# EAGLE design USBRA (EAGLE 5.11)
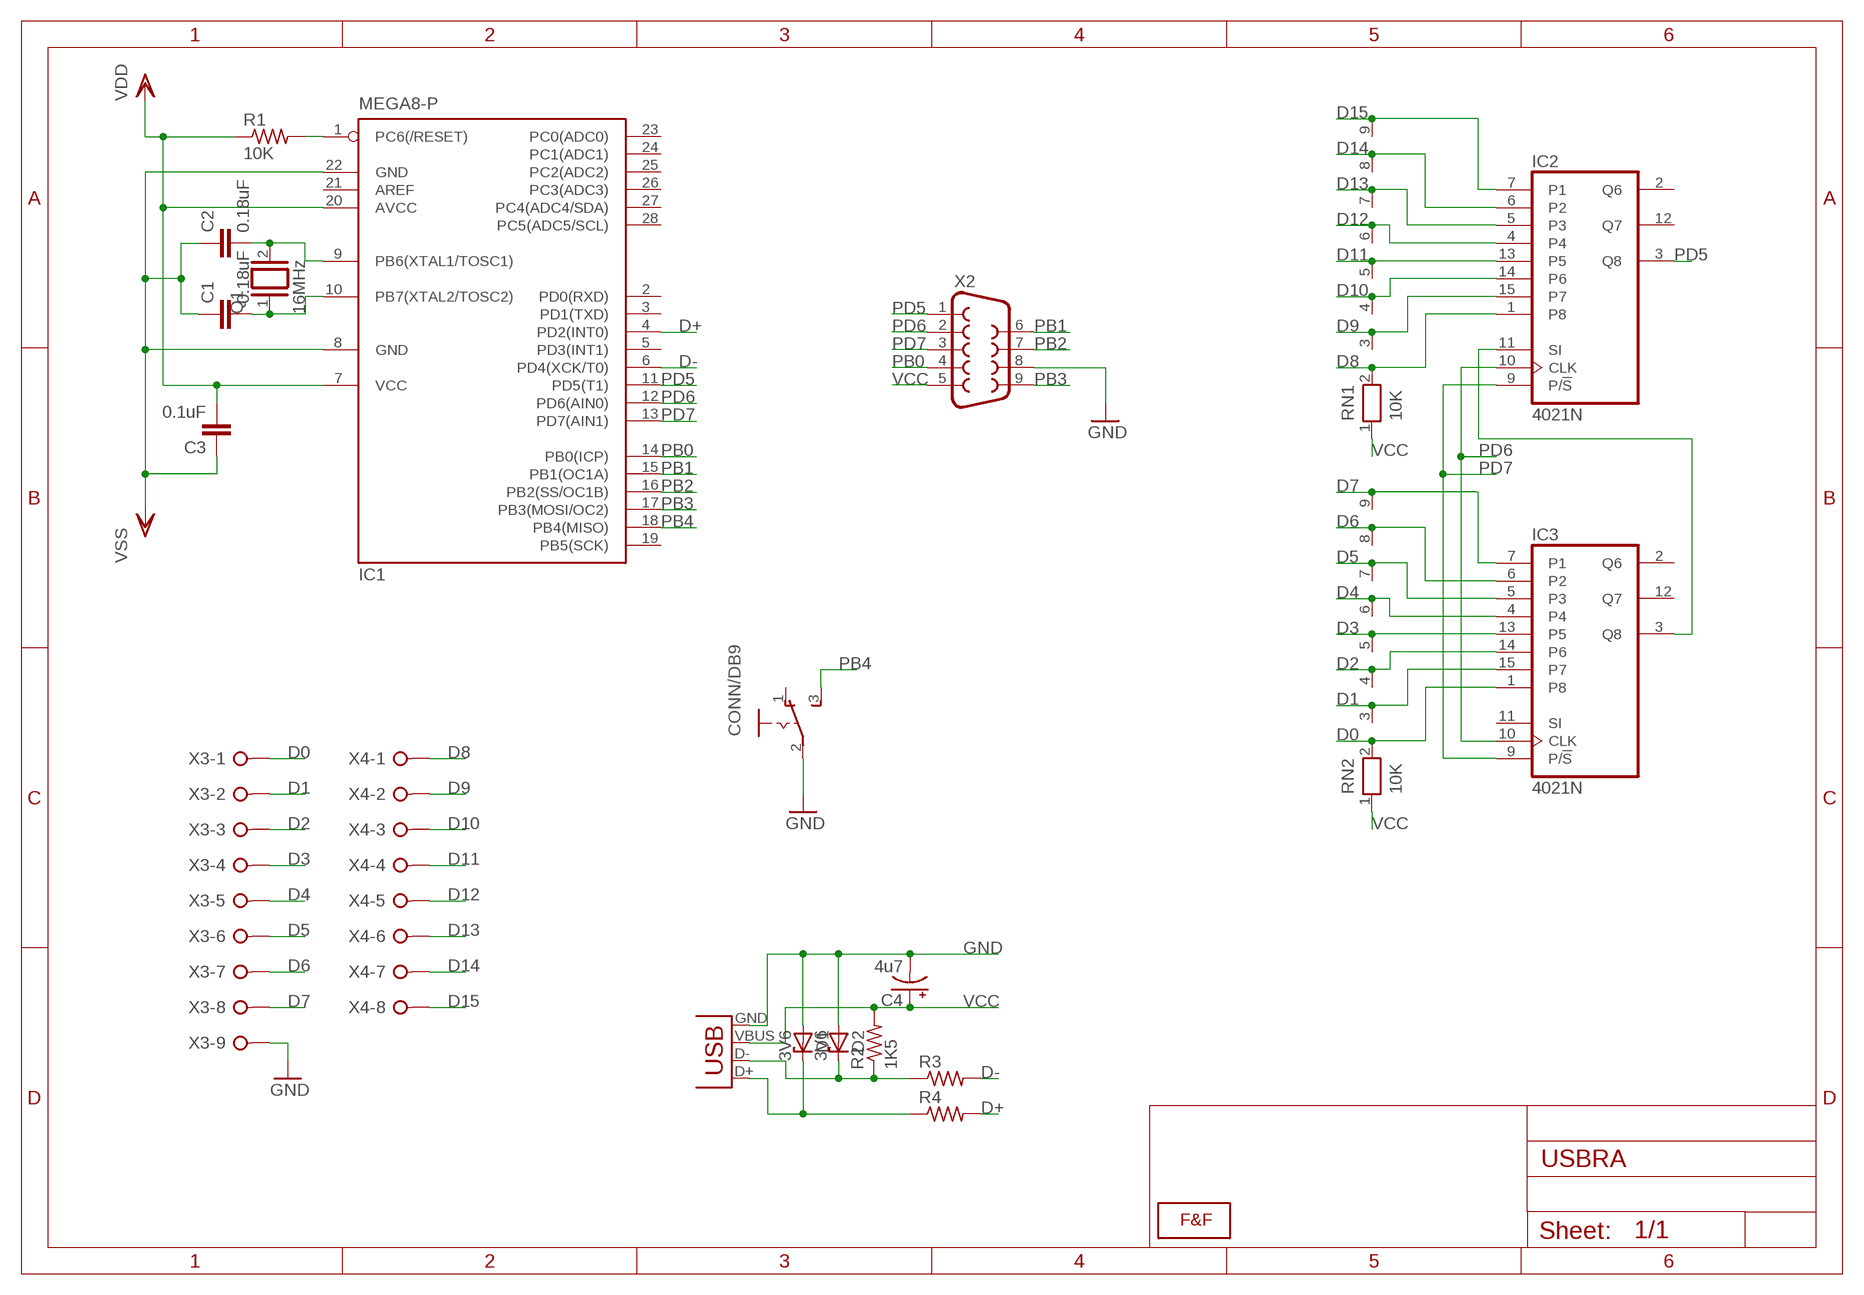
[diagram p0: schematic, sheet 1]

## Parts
C1  0.18uF  CAPPTH  [CAP-PTH-SMALL]
C2  0.18uF  CAPPTH  [CAP-PTH-SMALL]
C3  0.1uF  CAPPTH  [CAP-PTH-SMALL]
C4  4u7  CPOL-USE2.5-6  [E2,5-6]
CONN/DB9  CHAVE  [CHAVE]
D1  3V6  ZENER-DIODEF126-12  [F126Z12]
D2  3V6  ZENER-DIODEF126-12  [F126Z12]
IC1  MEGA8-P  [DIL28-3]
IC2  4021N  [DIL16]
IC3  4021N  [DIL16]
Q1  16MHz  XTAL/S  [QS]
R1  10K  R-US_0207/10  [0207/10]
R2  1K5  R-US_0207/10  [0207/10]
R3  R-US_0207/10  [0207/10]
R4  R-US_0207/10  [0207/10]
RN1  10K  RN08  [RN-9]
RN2  10K  RN08  [RN-9]
U$1  LOGOLOGO_WITH_SMOKE_BIG  [LOGO_BIG]
X1  USBPTH  [USB-B-PTH]
X2  DB9MALE  [DB9_MALE]
X3  W237-09P  [W237-9P]
X4  W237-08P  [W237-8P]

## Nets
D0: IC3.1(P8) RN2.2 X3.1
D1: IC3.15(P7) RN2.3 X3.2
D2: IC3.14(P6) RN2.4 X3.3
D3: IC3.13(P5) RN2.5 X3.4
D4: IC3.4 RN2.6 X3.5
D5: IC3.5(P3) RN2.7 X3.6
D6: IC3.6(P2) RN2.8 X3.7
D7: IC3.7(P1) RN2.9 X3.8
D8: IC2.1(P8) RN1.2 X4.1
D9: IC2.15(P7) RN1.3 X4.2
D10: IC2.14(P6) RN1.4 X4.3
D11: IC2.13(P5) RN1.5 X4.4
D12: IC2.4 RN1.6 X4.5
D13: IC2.5(P3) RN1.7 X4.6
D14: IC2.6(P2) RN1.8 X4.7
D15: IC2.7(P1) RN1.9 X4.8
D+: IC1.4(PD2(INT0)) R4.2
D-: IC1.6(PD4(XCK/T0)) R3.2
GND: C1.1 C2.1 C3.1 C4.- CONN/DB9.2(P) D1.A D2.A IC1.8(GND) IC1.22(GND) X1.GND X2.8 X3.9 ; supply symbol labelled VSS
N$1: IC1.1(PC6(/RESET)) R1.2
N$2: C2.2 IC1.9(PB6(XTAL1/TOSC1)) Q1.2
N$3: C1.2 IC1.10(PB7(XTAL2/TOSC2)) Q1.1
N$4: IC2.11(SI) IC3.3(Q8)
N$8: D1.C R4.1 X1.D+
N$9: D2.C R2.1 R3.1 X1.D-
PB0: IC1.14(PB0(ICP)) X2.4
PB1: IC1.15(PB1(OC1A)) X2.6
PB2: IC1.16(PB2(SS/OC1B)) X2.7
PB3: IC1.17(PB3(MOSI/OC2)) X2.9
PB4: CONN/DB9.3(S) IC1.18(PB4(MISO))
PD5: IC1.11(PD5(T1)) IC2.3(Q8) X2.1
PD6: IC1.12(PD6(AIN0)) IC2.10(CLK) IC3.10(CLK) X2.2
PD7: IC1.13(PD7(AIN1)) IC2.9(P/!S) IC3.9(P/!S) X2.3
VCC: C3.2 C4.+ IC1.7(VCC) IC1.20(AVCC) R1.1 R2.2 RN1.1 RN2.1 X1.VBUS X2.5 ; supply symbol labelled VDD
Unconnected: CONN/DB9.1(O) IC1.2(PD0(RXD)) IC1.3(PD1(TXD)) IC1.5(PD3(INT1)) IC1.19(PB5(SCK)) IC1.21(AREF) IC1.23(PC0(ADC0)) IC1.24(PC1(ADC1)) IC1.25(PC2(ADC2)) IC1.26(PC3(ADC3)) IC1.27(PC4(ADC4/SDA)) IC1.28(PC5(ADC5/SCL)) IC2.2(Q6) IC2.12(Q7) IC3.2(Q6) IC3.11(SI) IC3.12(Q7)

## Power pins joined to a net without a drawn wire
GND: IC2.8(VSS) IC3.8(VSS)
VCC: IC2.16(VDD) IC3.16(VDD)

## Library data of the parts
C1-C3 = SparkFun:CAP: Capacitor
C4 = adafruit:CPOL-US: POLARIZED CAPACITOR, American symbol
CONN/DB9 = switch-fef:CHAVE: chave Verificar
D1 D2 = diode:ZENER-DIODE: Z-Diode
IC1 = atmel:MEGA8-P: MICROCONTROLLER 8 Kbytes FLASH, 1 kbytes SRAM, 512 bytes EEPROM, USART, 4-channel 10 bit ADC, 2-channel 8 bit ADC Pin compatible with Atmega48, ATMega88, ATMega168 Source: avr.lbr; OC_FARNELL: unknown; OC_NEWARK: unknown
IC2 IC3 = 40xx:4021: 8-bit static SHIFT REGISTER
Q1 = special:XTAL/S: CRYSTAL
R1-R4 = adafruit:R-US_: RESISTOR, American symbol
RN1 RN2 = resistor-net:RN08: RESISTOR NETWORK; OC_FARNELL: unknown; OC_NEWARK: unknown
U$1 = F&F:LOGO: Faísca e Fumaça Logo
X1 = SparkFun:USB: USB Connectors USB-B-PTH is fully proven SKU : PRT-00139 USB-miniB is fully proven SKU : PRT-00587 USB-A-PCB is untested. USB-A-H is throughly reviewed, but untested. Spark Fun Electronics SKU : PRT-00437 USB-B-SMT is throughly reviewed, but untested. Needs silkscreen touching up. USB-A-S has not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
X2 = SparkFun:DB9: DB9 Connector Standard DB9 (D-Sub 9) serial connector. Can be used for CAN bus as well as RS485 and RS232. Footprint production proven. Spark Fun Electronics SKU : PRT-00429
X3 = con-wago-508:W237-09P: WAGO SREW CLAMP; OC_FARNELL: unknown; OC_NEWARK: unknown
X4 = con-wago-508:W237-08P: WAGO SREW CLAMP; OC_FARNELL: unknown; OC_NEWARK: unknown

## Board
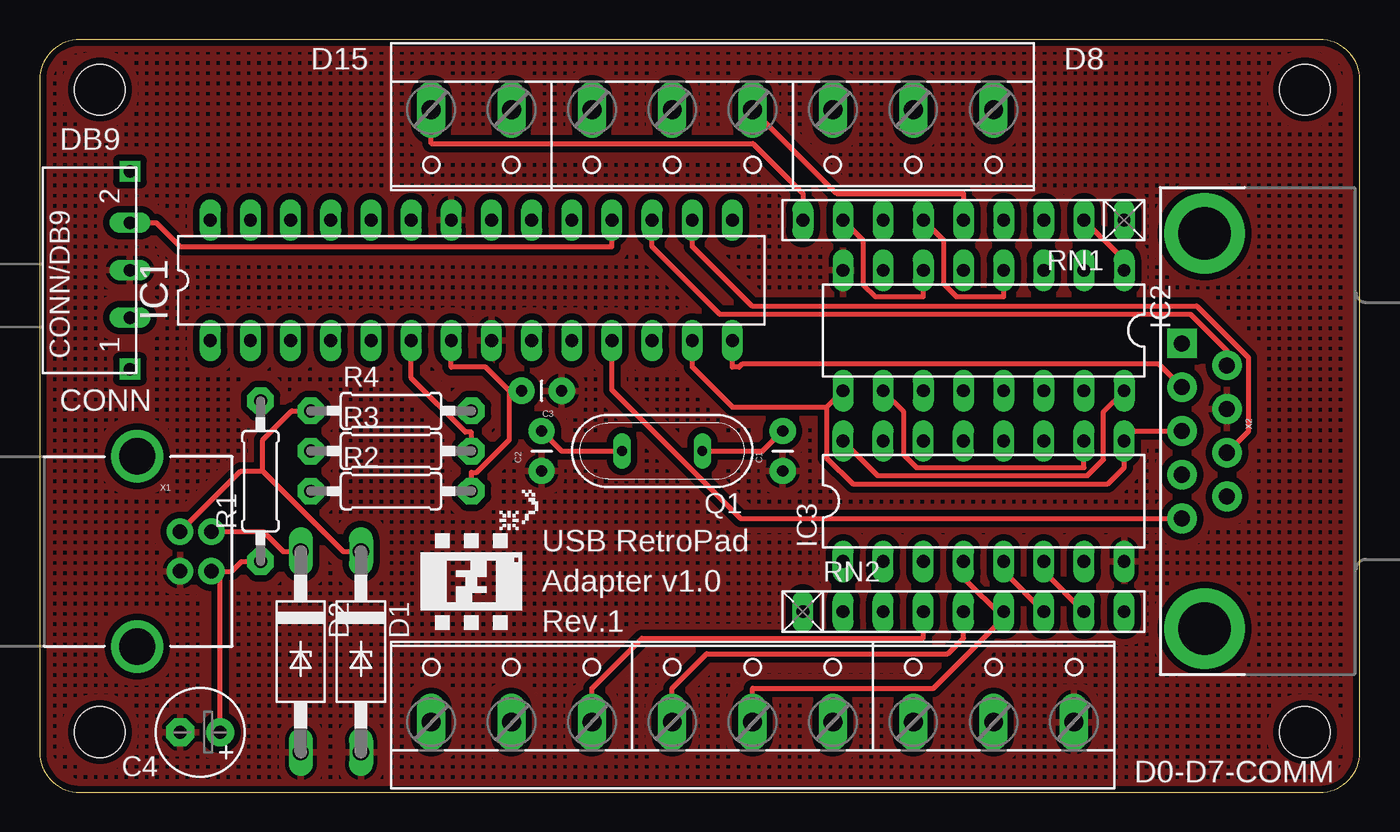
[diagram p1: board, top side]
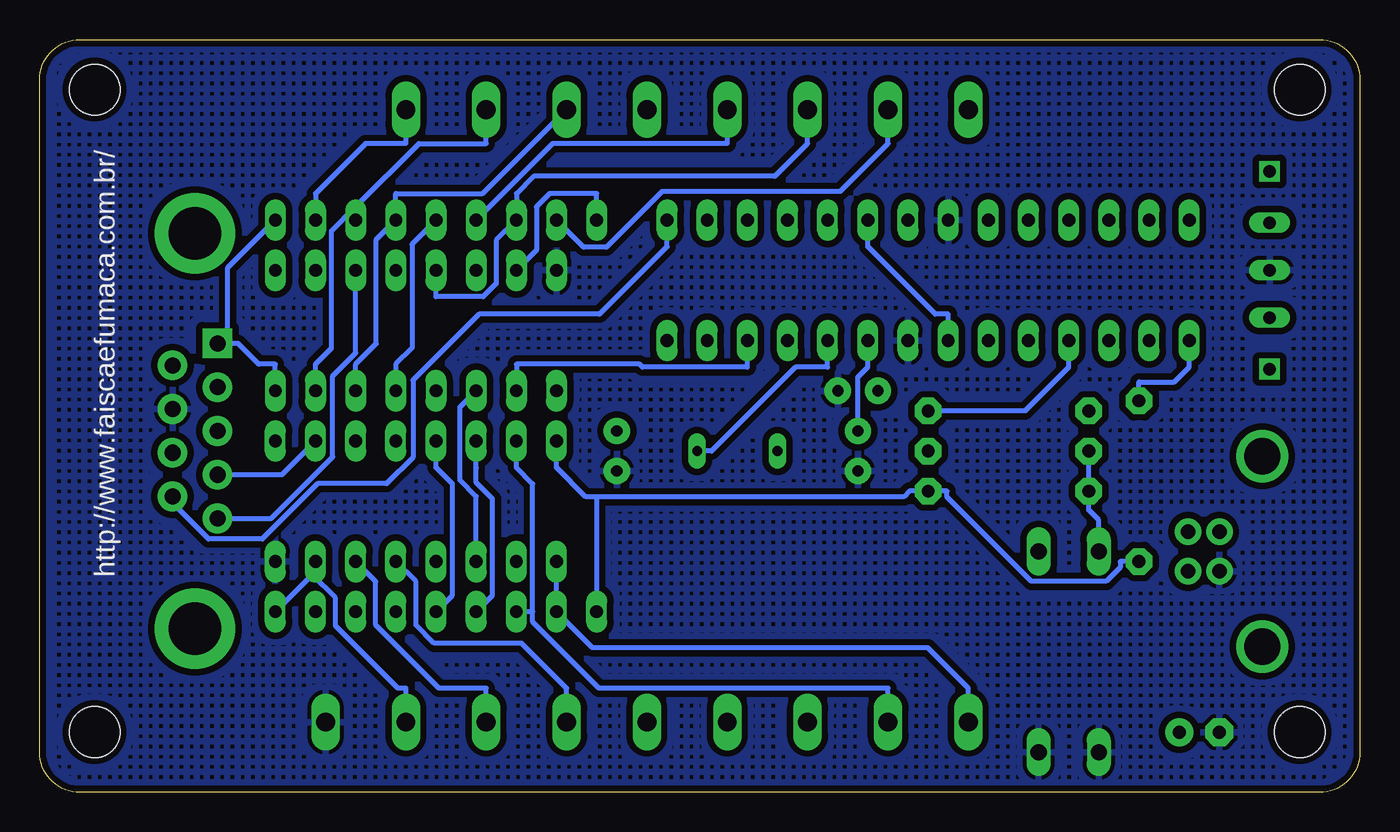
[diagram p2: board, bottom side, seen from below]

Size 83.49 x 47.62 mm. Coordinates in mm from the lower left corner, seen from the top.
Outline: 83.49,45.08 arc90 80.95,47.62 2.54,47.62 arc90 0,45.08 0,2.54 arc90 2.54,0 80.95,0 arc90 83.49,2.54 83.49,45.08
Copper layers (1*16): Top 0.035mm / dielectric 1.5mm / Bottom 0.035mm
Design rules "Fusion_eagle_rule_v1.1": minimum track width 6mil, minimum drill 12mil, track to track 6mil, track to pad 6mil, pad to pad 6mil, via to via 6mil, smd to smd 0mil, copper to edge 10mil, drill to drill 10mil, minimum pad ring 10mil, minimum via ring 6mil, stop-mask expansion 2mil, vias tented up to drill 100mil, thermal gap 10mil
Holes 3.2 mm at 3.81,44.45 3.81,3.81 80.01,44.45 80.01,3.81

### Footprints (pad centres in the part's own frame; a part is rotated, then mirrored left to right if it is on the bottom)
CAP-PTH-SMALL = drill 0.7 pad 1.651 round: 1 0,0; 2 2.54,0
E2,5-6 = drill 0.813 pad 1.778 round: + -1.27,0 | drill 0.813 pad 1.778 octagon: - 1.27,0
CHAVE = drill 0.8 long: 1 -3,0; 2 0,0; 3 3,0 | drill 0.8 square: P$1 -6.25,0; P$2 6.25,0
F126Z12 = drill 1.016 long: A 6.35,0; C -6.35,0
DIL28-3 = drill 0.813 long: 1 -16.51,-3.81; 2 -13.97,-3.81; 3 -11.43,-3.81; 4 -8.89,-3.81; 5 -6.35,-3.81; 6 -3.81,-3.81; 7 -1.27,-3.81; 8 1.27,-3.81; 9 3.81,-3.81; 10 6.35,-3.81; 11 8.89,-3.81; 12 11.43,-3.81; 13 13.97,-3.81; 14 16.51,-3.81; 15 16.51,3.81; 16 13.97,3.81; 17 11.43,3.81; 18 8.89,3.81; 19 6.35,3.81; 20 3.81,3.81; 21 1.27,3.81; 22 -1.27,3.81; 23 -3.81,3.81; 24 -6.35,3.81; 25 -8.89,3.81; 26 -11.43,3.81; 27 -13.97,3.81; 28 -16.51,3.81
DIL16 = drill 0.813 long: 1 -8.89,-3.81; 2 -6.35,-3.81; 3 -3.81,-3.81; 4 -1.27,-3.81; 5 1.27,-3.81; 6 3.81,-3.81; 7 6.35,-3.81; 8 8.89,-3.81; 9 8.89,3.81; 10 6.35,3.81; 11 3.81,3.81; 12 1.27,3.81; 13 -1.27,3.81; 14 -3.81,3.81; 15 -6.35,3.81; 16 -8.89,3.81
QS = drill 0.61 long: 1 -2.54,0; 2 2.54,0
0207/10 = drill 0.813 pad 1.676 octagon: 1 -5.08,0; 2 5.08,0
RN-9 = drill 0.813 long: 1 -10.16,0; 2 -7.62,0; 3 -5.08,0; 4 -2.54,0; 5 0,0; 6 2.54,0; 7 5.08,0; 8 7.62,0; 9 10.16,0
USB-B-PTH = drill 0.914 pad 1.676 round: D+ 0,1.25; D- 1.981,1.25; GND 0,-1.25; VBUS 1.981,-1.25 | drill 2.286 round: S1 -2.718,-6.02; S2 -2.718,6.02
DB9_MALE = drill 1.016 pad 1.88 round: 1 5.54,-1.42; 2 2.77,-1.42; 3 0,-1.42; 4 -2.77,-1.42; 6 4.15,1.42; 7 1.38,1.42; 8 -1.38,1.42; 9 -4.15,1.42 | drill 1.016 pad 1.88 square: 5 -5.54,-1.42 | drill 3.302 pad 5.08 round: G1 -12.5,0; G2 12.5,0
W237-9P = drill 1.194 long: 1 -20.32,-0.635; 2 -15.24,-0.635; 3 -10.16,-0.635; 4 -5.08,-0.635; 5 0,-0.635; 6 5.08,-0.635; 7 10.16,-0.635; 8 15.24,-0.635; 9 20.32,-0.635
W237-8P = drill 1.194 long: 1 -17.78,-0.635; 2 -12.7,-0.635; 3 -7.62,-0.635; 4 -2.54,-0.635; 5 2.54,-0.635; 6 7.62,-0.635; 7 12.7,-0.635; 8 17.78,-0.635

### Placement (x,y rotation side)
C1  46.99,20.32 90 top
C2  31.75,20.32 90 top
C3  33.02,25.4 180 top
C4  10.16,3.81 180 top
CONN/DB9  5.71,33.02 90 top
D1  20.32,8.89 270 top
D2  16.51,8.89 270 top
IC1  27.3,32.38 0 top
IC2  59.69,29.21 180 top
IC3  59.69,18.41 0 top
Q1  39.37,21.59 180 top
R1  13.97,19.68 90 top
R2  22.23,19.05 0 top
R3  22.23,21.59 0 top
R4  22.23,24.13 0 top
RN1  58.42,36.2 180 top
RN2  58.42,11.43 0 top
U$1  27.3,13.34 0 top
X1  8.89,15.24 0 top
X2  73.66,22.86 270 top
X3  45.09,5.08 0 top
X4  42.55,42.55 180 top

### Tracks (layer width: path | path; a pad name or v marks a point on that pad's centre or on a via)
D0
  Bottom 0.305: IC3.1 RN2.2 48.53,9.16 27.33,9.16 24.77,6.59 X3.1
D1
  Bottom 0.305: 52.31,11.43 RN2.3 | 52.31,11.43 52.31,10.79 48.12,6.59 29.84,6.59 X3.2 | 52.31,11.43 | 52.31,11.43 52.31,19.52 53.34,20.55 IC3.15
D2
  Top 0.305: X3.3 34.92,6.59 38.09,9.75 55.88,9.75 RN2.4
  Bottom 0.305: RN2.4 54.86,12.45 54.86,18.57 55.88,19.59 55.88,20.55 IC3.14
D3
  Top 0.305: RN2.5 58.42,9.75 57.43,8.76 42.17,8.76 40.01,6.59 X3.4
  Bottom 0.305: IC3.13 58.42,20.55 57.39,19.52 57.39,12.46 RN2.5
D4
  Top 0.305: X3.5 45.09,6.59 56.52,6.59 60.96,11.03 | 60.96,11.03 58.42,13.57 IC3.4 | 60.96,11.03 RN2.6
D5
  Top 0.305: RN2.7 60.96,13.97 IC3.5
  Bottom 0.305: X3.6 50.16,6.59 53,9.43 58.53,9.43 59.69,10.59 59.69,13.34 IC3.5
D6
  Top 0.305: RN2.8 63.5,13.97 IC3.6
  Bottom 0.305: X3.7 55.24,6.59 58.23,6.59 62.23,10.59 62.23,13.34 IC3.6
D7
  Bottom 0.305: 66.24,13.77 66.04,13.97 IC3.7 | 66.24,13.77 RN2.9 | 66.24,13.77 64.77,12.29 64.77,10.54 60.82,6.59 60.33,6.59 X3.8
D8
  Top 0.305: RN1.2 68.58,33.66 IC2.1
  Bottom 0.305: RN1.2 66.04,37.87 62.88,41.03 60.33,41.03 X4.1
D9
  Bottom 0.305: X4.2 55.24,41.03 59.5,41.03 63.5,37.03 | 63.5,37.03 65.02,35.51 65.02,28.09 66.04,27.08 IC2.15 | 63.5,37.03 RN1.3
D10
  Bottom 0.305: X4.3 55.47,37.87 60.96,37.87 RN1.4 62.19,34.96 62.19,28.38 63.5,27.08 IC2.14
D11
  Top 0.305: RN1.5 58.42,37.87 50.39,37.87 X4.4
  Bottom 0.305: IC2.13 60.96,27.08 59.94,28.09 59.94,34.67 RN1.5
D12
  Top 0.305: IC2.4 60.96,31.34 57.97,31.34 57.15,32.17 57.15,34.92 RN1.6
  Bottom 0.305: X4.5 40.01,41.03 51.04,41.03 RN1.6
D13
  Bottom 0.305: X4.6 34.92,41.03 37,38.96 52.25,38.96 53.34,37.87 RN1.7 54.61,34.92 54.61,32.17 55.44,31.34 58.42,31.34 IC2.5
D14
  Top 0.305: IC2.6 55.88,31.34 52.85,31.34 52.07,32.13 52.07,34.92 RN1.8
  Bottom 0.305: RN1.8 49.09,34.48 47.65,34.48 44.12,38.01 32.87,38.01 29.84,41.03 X4.7
D15
  Top 0.305: RN1.9 48.26,37.87 45.1,41.03 24.77,41.03 X4.8
  Bottom 0.305: RN1.9 48.26,37.87 51.24,37.87 52.07,37.04 52.07,34.29 IC2.7
D+
  Bottom 0.305: IC1.4 18.41,26.9 21.18,24.13 R4.2
D-
  Top 0.305: R3.2 27.3,22.78 26.93,22.78 23.5,26.22 IC1.6
GND
  pour Top (isolate 0.406, hatched): 0,46.99 83.82,46.99 83.82,0 0,0
  pour Bottom (isolate 0.406, hatched): 0,46.99 83.82,46.99 83.82,0 0,0
N$1
  Bottom 0.305: IC1.1 10.79,26.9 11.73,25.96 13.97,25.96 R1.2
N$2
  Top 0.305: Q1.2 33.02,21.59 C2.2
  Bottom 0.305: IC1.9 31.11,26.9 31.75,26.26 C2.2
N$3
  Top 0.305: Q1.1 45.72,21.59 C1.2
  Bottom 0.305: Q1.1 40.99,21.59 35.69,26.9 33.66,26.9 IC1.10
N$4
  Bottom 0.305: IC3.3 55.88,18.73 56.91,19.76 56.91,24.37 IC2.11
N$8
  Top 0.305: 14.12,20.32 19.2,15.24 D1.C | X1.D+ 12.72,20.32 14.12,20.32 | 14.12,20.32 14.12,22.3 15.95,24.13 R4.1
N$9
  Top 0.305: D2.C 15.39,15.24 14.14,16.49 X1.D-
  Bottom 0.305: D2.C 16.51,17.22 17.14,17.86 R2.1 R3.1
PB0
  Top 0.305: IC1.14 43.81,26.9 44.24,26.9 44.46,27.12 70.75,27.12 X2.4
PB1
  Bottom 0.305: IC1.15 43.81,34.52 48.08,30.25 55.69,30.25 59.87,26.07 59.87,21.19 61.53,19.53 65.9,19.53 69.4,16.02 72.8,16.02 75.08,18.3 X2.6
PB2
  Top 0.305: IC1.16 41.27,34.52 45.03,30.76 73.17,30.76 76.44,27.49 76.44,22.84 X2.7
PB3
  Top 0.305: IC1.17 38.73,34.52 43,30.25 72.77,30.25 75.08,27.95 X2.9
PB4
  Top 0.305: CONN/DB9.3 7.38,36.02 8.88,34.52 36.2,34.52 IC1.18
PD5
  Top 0.305: X2.1 44.32,17.32 36.2,25.45 IC1.11
  Bottom 0.305: X2.1 68.85,17.32 64.95,21.22 64.95,26.34 63.5,27.8 IC2.3
PD6
  Top 0.305: IC3.10 66.04,20.55 55.43,20.55 54.61,21.37 54.61,24.13 IC2.10
  Bottom 0.305: IC1.12 38.73,26.9 45.37,26.9 45.54,27.08 53.34,27.08 IC2.10 | X2.2 68.17,20.09 IC3.10
PD7
  Top 0.305: 49.77,24.37 IC2.9 | 49.77,24.37 49.77,21.16 51.42,19.51 67.54,19.51 68.58,20.55 IC3.9 69.22,22.86 X2.3 | 49.77,24.37 43.8,24.37 41.27,26.9 IC1.13
VCC
  Top 0.305: IC2.16 67.28,24.1 67.28,21.05 66.26,20.04 52.99,20.04 IC3.16 | 29.71,25.4 29.71,22.31 27.65,20.24 27.3,20.24 R2.2 | 29.71,25.4 28.21,26.9 26.04,26.9 IC1.7 | 29.71,25.4 C3.2 | 11.43,13.99 12.16,13.99 12.78,14.61 R1.1 | 11.43,13.99 X1.VBUS | C4.+ 11.43,13.99
  Bottom 0.305: 48.26,18.7 28.85,18.7 28.5,19.05 R2.2 26.11,19.05 26.11,18.68 20.79,13.36 16.04,13.36 15.16,14.23 15.16,14.61 R1.1 | 48.26,18.7 48.95,18.7 50.8,20.55 IC3.16 | 48.26,18.7 RN2.1 | IC1.7 26.04,30.25 26.85,30.25 31.11,34.52 IC1.20 | 71.59,28.4 71.59,33.18 RN1.1 | 71.59,28.4 70.94,28.4 69.62,27.08 68.58,27.08 IC2.16 | 71.59,28.4 X2.5

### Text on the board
tPlace: D15 | D8 | DB9 | CONN | USB RetroPad | Adapter v1.0 | Rev.1 | D0-D7-COMM
bPlace: http://www.faiscaefumaca.com.br/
